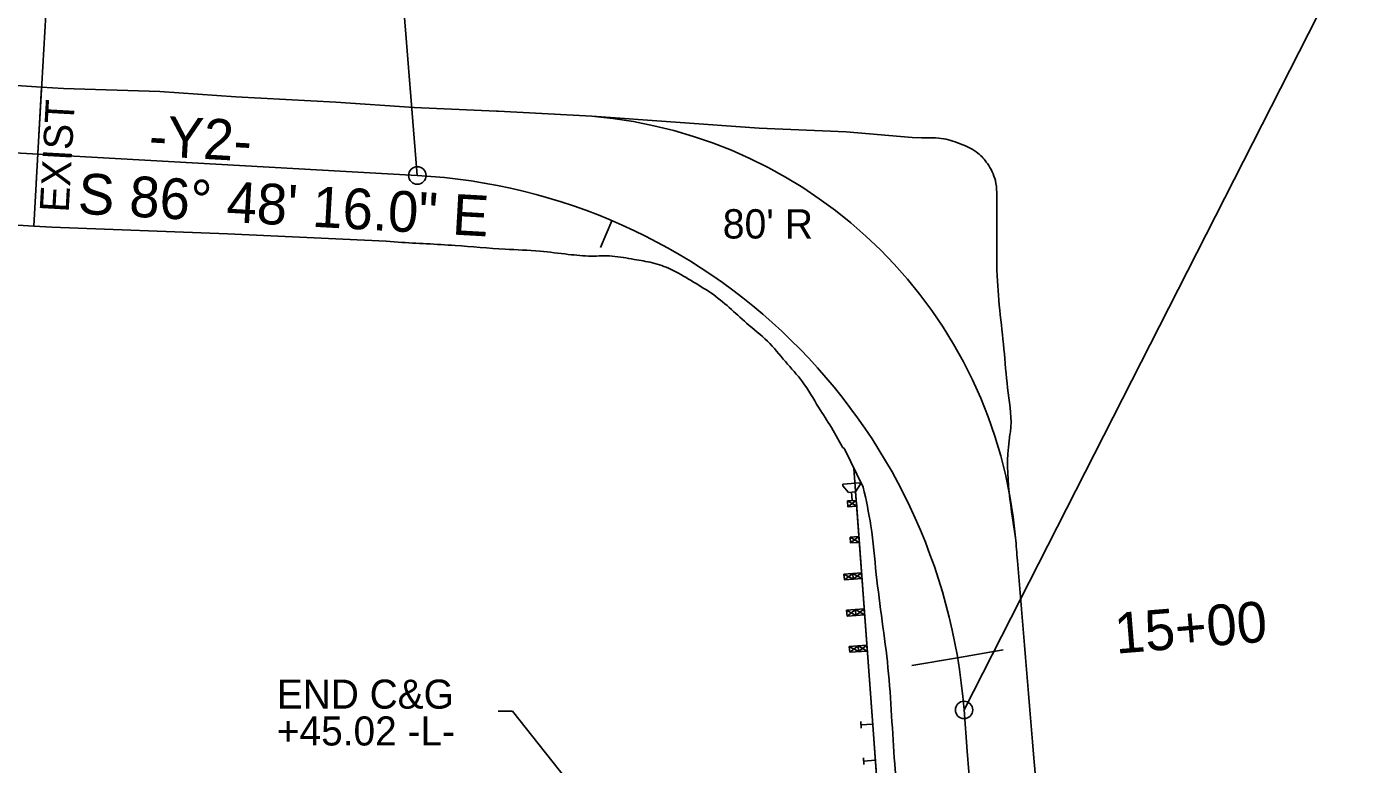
# Model space of a CAD drawing. Extents: x 1616561 to 1622460, y 896726 to 899651.
# Drawn here: x 1619756.7 to 1619984.9, y 898094.7 to 898221.7 of the extents above; entities that cross this region are included whole.
import ezdxf

# ---------------------------------------------------------------- set-up
doc = ezdxf.new("R2010")
doc.units = 0
for name, color, linetype in [('Old_Level_3', 7, 'Continuous'), ('Prop Conc Curb and Gutter', 7, 'Continuous'), ('Prop Dimension', 7, 'Continuous'), ('Prop DSN Text', 7, 'Continuous'), ('Prop Guardrail', 7, 'Continuous'), ('Prop Guardrail Anchor Unit CELL', 7, 'Continuous'), ('Prop Rem of Exist Asph Pvmt', 7, 'Continuous'), ('Prop Shade Light', 7, 'Continuous'), ('Prop Structure Anchor Unit CELL', 7, 'Continuous'), ('Prop Superelevation  Arrow CELL', 7, 'Continuous'), ('Prop Superelevation Label', 7, 'Continuous'), ('Prop Terminator CELL', 7, 'Continuous'), ('Scratch_Level_1', 7, 'Continuous'), ('Sheet Cutting Line CELL', 7, 'Continuous'), ('Sheet North Arrow CELL', 7, 'Continuous')]:
    doc.layers.add(name, color=color, linetype=linetype)

msp = doc.modelspace()

# ---------------------------------------------------------------- linework, layer by layer
at = {"layer": 'Old_Level_3'}
msp.add_arc((1619799.51, 898841.24), 791.25, 245.11013, 270, dxfattribs=at)
at = {"layer": 'Prop Conc Curb and Gutter'}
for p, q in [((1619757.95, 898187.36), (1619759.28, 898211.29)), ((1619837.57, 898207.15), (1619837.89, 898207.19)), ((1619853.99, 898206.29), (1619853.99, 898206.29)), ((1619897.18, 898149.35), (1619895.28, 898152.75)), ((1619897.48, 898149.06), (1619897.18, 898149.35)), ((1619900.73, 898142.48), (1619897.48, 898149.06))]:
    msp.add_line(p, q, dxfattribs=at)
for points in [[(1619759.28, 898211.29), (1619763.07, 898211.07), (1619779.65, 898210.53), (1619792.7, 898209.63), (1619809.95, 898208.73), (1619823.44, 898207.8), (1619837.57, 898207.15)], [(1619837.89, 898207.19), (1619853.99, 898206.29)], [(1619761.02, 898187.22), (1619757.95, 898187.36)], [(1619820.66, 898184.6), (1619818.58, 898184.81), (1619791.26, 898186.06), (1619761.02, 898187.22)]]:
    msp.add_lwpolyline(points, dxfattribs=at)
msp.add_arc((1619847.28, 898126.57), 80, 5.1565, 85.1875, dxfattribs=at)
for points in [[(1619895.28, 898152.75), (1619893.04, 898156.2), (1619890.25, 898160.6), (1619887.34, 898164.06), (1619884.22, 898167.59), (1619880.64, 898170.68), (1619877.64, 898173.39), (1619874.58, 898175.82), (1619871.08, 898178.01), (1619867.57, 898179.96), (1619864.43, 898181.07), (1619861.28, 898181.65), (1619857.51, 898182.22), (1619853.92, 898182.23), (1619849.94, 898182.52), (1619845.07, 898183.06), (1619839.09, 898183.42), (1619830.47, 898184.04), (1619820.66, 898184.6)], [(1619912.86, 898014.62), (1619911.74, 898030.35), (1619910.49, 898046.49), (1619909.25, 898062.87), (1619907.77, 898079.01), (1619906.15, 898094.87), (1619904.98, 898111.37), (1619902.97, 898127.44), (1619902.03, 898135.82), (1619900.73, 898142.48)], [(1619926.95, 898133.76), (1619927.27, 898129.8), (1619930.05, 898096.53), (1619932.69, 898064.69), (1619935.3, 898031.6), (1619938.16, 897995.71), (1619939.79, 897970.86), (1619940.42, 897963.24), (1619941.13, 897955.62), (1619942.39, 897940.38), (1619944.78, 897896.12), (1619947, 897859.54)]]:
    msp.add_spline(points, degree=3, dxfattribs=at)
at = {"layer": 'Prop DSN Text'}
for p, q in [((1619837.85, 898103.91), (1619840.34, 898103.9)), ((1619840.34, 898103.9), (1619872, 898063.99))]:
    msp.add_line(p, q, dxfattribs=at)
at = {"layer": 'Prop Guardrail'}
msp.add_line((1619901.38, 898114.76), (1619902.3, 898102.29), dxfattribs=at)
at = {"layer": 'Prop Guardrail Anchor Unit CELL'}
for p, q in [((1619900.15, 898143.2), (1619897.22, 898142.98)), ((1619897.24, 898142.67), (1619897.22, 898142.98)), ((1619897.24, 898142.67), (1619898.18, 898141.56)), ((1619898.18, 898141.56), (1619899.41, 898141.65)), ((1619898.69, 898141.6), (1619898.8, 898140.14)), ((1619899.41, 898141.65), (1619900.18, 898142.89)), ((1619899.52, 898140.19), (1619899.41, 898141.65)), ((1619900.18, 898142.89), (1619900.15, 898143.2)), ((1619899.53, 898140.19), (1619898.01, 898140.08)), ((1619898.08, 898139.08), (1619898.01, 898140.08)), ((1619899.6, 898139.19), (1619898.01, 898140.08)), ((1619898.08, 898139.08), (1619899.53, 898140.19)), ((1619899.6, 898139.19), (1619898.08, 898139.08)), ((1619899.6, 898139.19), (1619899.53, 898140.19)), ((1619899.56, 898139.69), (1619901.38, 898114.76)), ((1619899.98, 898133.96), (1619898.47, 898133.84)), ((1619900.05, 898132.96), (1619898.47, 898133.85)), ((1619898.54, 898132.85), (1619898.47, 898133.84)), ((1619898.54, 898132.85), (1619899.98, 898133.96)), ((1619900.05, 898132.96), (1619898.54, 898132.85)), ((1619900.05, 898132.96), (1619899.98, 898133.96)), ((1619900.44, 898127.72), (1619897.41, 898127.5)), ((1619897.48, 898126.5), (1619897.41, 898127.5)), ((1619897.41, 898127.5), (1619898.99, 898126.61)), ((1619898.92, 898127.61), (1619897.48, 898126.5)), ((1619898.99, 898126.61), (1619898.92, 898127.61)), ((1619900.51, 898126.72), (1619898.92, 898127.61)), ((1619898.99, 898126.61), (1619900.44, 898127.72)), ((1619900.51, 898126.72), (1619900.44, 898127.72)), ((1619900.51, 898126.72), (1619897.48, 898126.5)), ((1619900.89, 898121.49), (1619897.86, 898121.27)), ((1619897.94, 898120.27), (1619897.86, 898121.27)), ((1619897.86, 898121.27), (1619899.45, 898120.38)), ((1619899.38, 898121.38), (1619897.94, 898120.27)), ((1619900.96, 898120.49), (1619897.94, 898120.27)), ((1619899.45, 898120.38), (1619899.38, 898121.38)), ((1619900.96, 898120.49), (1619899.38, 898121.38)), ((1619899.45, 898120.38), (1619900.89, 898121.49)), ((1619900.96, 898120.49), (1619900.89, 898121.49)), ((1619901.34, 898115.25), (1619898.32, 898115.03)), ((1619898.39, 898114.04), (1619898.32, 898115.03)), ((1619898.32, 898115.03), (1619899.9, 898114.15)), ((1619899.83, 898115.14), (1619898.39, 898114.04)), ((1619901.42, 898114.26), (1619898.39, 898114.04)), ((1619899.9, 898114.15), (1619899.83, 898115.14)), ((1619901.42, 898114.26), (1619899.83, 898115.14)), ((1619899.9, 898114.15), (1619901.34, 898115.25)), ((1619901.42, 898114.26), (1619901.34, 898115.25))]:
    msp.add_line(p, q, dxfattribs=at)
at = {"layer": 'Prop Rem of Exist Asph Pvmt'}
msp.add_lwpolyline([(1619853.99, 898206.29), (1619882.82, 898204.22), (1619897.78, 898203.59), (1619909.14, 898202.64), (1619910.78, 898202.56)], dxfattribs=at)
msp.add_arc((1619847.28, 898126.57), 80, 5.1565, 85.1875, dxfattribs=at)
msp.add_spline([(1619910.78, 898202.56), (1619914.61, 898202.41), (1619917.69, 898201.44), (1619920.47, 898199.96), (1619922.09, 898198.16), (1619923.47, 898195.21), (1619923.71, 898191.11), (1619923.71, 898187), (1619923.78, 898178.81), (1619924.32, 898172.1), (1619925.02, 898165.39), (1619925.67, 898158.69), (1619926.06, 898152), (1619925.98, 898151.51), (1619926.96, 898133.76)], degree=3, dxfattribs=at)
at = {"layer": 'Prop Shade Light'}
msp.add_line((1619900.73, 898142.48), (1619899.1, 898145.65), dxfattribs=at)
msp.add_lwpolyline([(1619899.1, 898145.65), (1619901.84, 898108.52), (1619902.76, 898096.06), (1619902.99, 898092.94), (1619903.22, 898089.82), (1619903.45, 898086.71), (1619903.56, 898085.15), (1619903.68, 898083.59), (1619903.79, 898082.03), (1619903.91, 898080.47), (1619904.02, 898078.92), (1619904.14, 898077.36), (1619904.14, 898077.35), (1619904.72, 898069.49)], dxfattribs=at)
msp.add_spline([(1619908.68, 898069.49), (1619907.77, 898079.01), (1619906.15, 898094.87), (1619904.98, 898111.37), (1619902.97, 898127.44), (1619902.03, 898135.82), (1619900.73, 898142.48)], degree=3, dxfattribs=at)
at = {"layer": 'Prop Structure Anchor Unit CELL'}
for p, q in [((1619904.13, 898077.36), (1619902.3, 898102.29)), ((1619900.39, 898100.97), (1619900.3, 898102.11)), ((1619902.34, 898101.69), (1619900.35, 898101.54)), ((1619900.85, 898094.74), (1619900.76, 898095.88)), ((1619902.8, 898095.45), (1619900.8, 898095.31))]:
    msp.add_line(p, q, dxfattribs=at)
at = {"layer": 'Prop Superelevation  Arrow CELL'}
for p, q in [((1619758.64, 898199.75), (1619758.36, 898194.76)), ((1619857.47, 898188.3), (1619855.51, 898183.7))]:
    msp.add_line(p, q, dxfattribs=at)
at = {"layer": 'Prop Superelevation Label'}
for q in [(1619924.84, 898114.45), (1619909.07, 898111.76)]:
    msp.add_line((1619916.96, 898113.1), q, dxfattribs=at)
at = {"layer": 'Prop Terminator CELL'}
for p, q in [((1619709.38, 898214.52), (1619759.28, 898211.29)), ((1619759.28, 898211.29), (1619757.95, 898187.36)), ((1619757.95, 898187.36), (1619759.28, 898211.29)), ((1619757.95, 898187.36), (1619759.28, 898211.29)), ((1619837.57, 898207.15), (1619837.89, 898207.19)), ((1619853.99, 898206.29), (1619853.99, 898206.29)), ((1619708.05, 898190.55), (1619757.95, 898187.36)), ((1619897.18, 898149.35), (1619895.28, 898152.75)), ((1619897.48, 898149.06), (1619897.18, 898149.35)), ((1619900.73, 898142.48), (1619897.48, 898149.06))]:
    msp.add_line(p, q, dxfattribs=at)
for points in [[(1619759.28, 898211.29), (1619763.07, 898211.07), (1619779.65, 898210.53), (1619792.7, 898209.63), (1619809.95, 898208.73), (1619823.44, 898207.8), (1619837.57, 898207.15)], [(1619837.89, 898207.19), (1619853.99, 898206.29)], [(1619761.02, 898187.22), (1619757.95, 898187.36)], [(1619820.66, 898184.6), (1619818.58, 898184.81), (1619791.26, 898186.06), (1619761.02, 898187.22)]]:
    msp.add_lwpolyline(points, dxfattribs=at)
msp.add_arc((1619847.28, 898126.57), 80, 5.1565, 85.1875, dxfattribs=at)
for points in [[(1619895.28, 898152.75), (1619893.04, 898156.2), (1619890.25, 898160.6), (1619887.34, 898164.06), (1619884.22, 898167.59), (1619880.64, 898170.68), (1619877.64, 898173.39), (1619874.58, 898175.82), (1619871.08, 898178.01), (1619867.57, 898179.96), (1619864.43, 898181.07), (1619861.28, 898181.65), (1619857.51, 898182.22), (1619853.92, 898182.23), (1619849.94, 898182.52), (1619845.07, 898183.06), (1619839.09, 898183.42), (1619830.47, 898184.04), (1619820.66, 898184.6)], [(1619912.86, 898014.62), (1619911.74, 898030.35), (1619910.49, 898046.49), (1619909.25, 898062.87), (1619907.77, 898079.01), (1619906.15, 898094.87), (1619904.98, 898111.37), (1619902.97, 898127.44), (1619902.03, 898135.82), (1619900.73, 898142.48)], [(1619926.95, 898133.76), (1619927.27, 898129.8), (1619930.05, 898096.53), (1619932.69, 898064.69), (1619935.3, 898031.6), (1619938.16, 897995.71), (1619939.79, 897970.86), (1619940.42, 897963.24), (1619941.13, 897955.62), (1619942.39, 897940.38), (1619944.78, 897896.12), (1619947, 897859.54)]]:
    msp.add_spline(points, degree=3, dxfattribs=at)
at = {"layer": 'Sheet Cutting Line CELL'}
msp.add_line((1619628.34, 898207.02), (1619823.96, 898196.1), dxfattribs=at)
for centre, radius, start, end in [((1619799.51, 898841.24), 800, 229.34838, 270), ((1619818.39, 898096.26), 100, 4.5086, 86.8045), ((1606187.46, 897021.41), 13773.24, 2.612111, 4.508639)]:
    msp.add_arc(centre, radius, start, end, dxfattribs=at)
at = {"layer": 'Sheet North Arrow CELL'}
for p, q in [((1619823.96, 898196.1), (1619805.89, 898417.67)), ((1619758.65, 898199.95), (1619769.46, 898393.5)), ((1620060.42, 898383.63), (1619918.08, 898104.12))]:
    msp.add_line(p, q, dxfattribs=at)
for centre in [(1619823.96, 898196.1), (1619918.08, 898104.12)]:
    msp.add_circle(centre, 1.5, dxfattribs=at)

# ---------------------------------------------------------------- texts
at = {"layer": 'Prop Dimension'}
for s, height, rotation, p in [('EXIST', 5, 86.8045, (1619763.93, 898189.67)), ('15+00', 7, 4.6326, (1619944.27, 898113.79))]:
    msp.add_text(s, height=height, rotation=rotation, dxfattribs=at).set_placement(p)
msp.add_text("80' R", height=5.044, dxfattribs=at).set_placement((1619876.54, 898185.25))
at = {"layer": 'Prop DSN Text'}
for s, p in [('END C&G', (1619799.78, 898104.34)), ('+45.02 -L-', (1619799.78, 898098))]:
    msp.add_text(s, height=5, dxfattribs=at).set_placement(p)
at = {"layer": 'Scratch_Level_1'}
for s, p in [('-Y2-', (1619777.63, 898199.49)), ('S 86%%d 48\' 16.0" E', (1619765.41, 898189.54))]:
    msp.add_text(s, height=7, rotation=356.8045, dxfattribs=at).set_placement(p)

doc.saveas('drawing.dxf')
